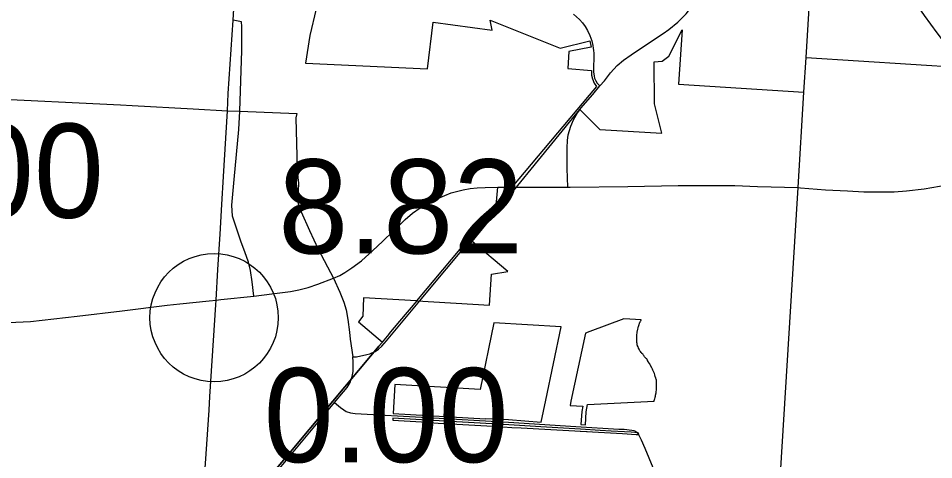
# Model space of a CAD drawing. Extents: x 1729596 to 1934326, y 644115 to 911751.
# Drawn here: x 1834509 to 1845211, y 778685 to 783844 of the extents above; entities that cross this region are included whole.
import ezdxf

# ---------------------------------------------------------------- set-up
doc = ezdxf.new("R2010")
doc.units = 0
for name, color, linetype in [('Default', 7, 'Continuous'), ('GM_X_City_Street', 7, 'Continuous'), ('GM_X_Corporation', 7, 'Continuous'), ('GM_X_County_Road', 7, 'Continuous'), ('GM_X_Interstate_Route', 7, 'Continuous'), ('GM_X_State_Route', 7, 'Continuous'), ('GM_X_Township', 7, 'Continuous')]:
    doc.layers.add(name, color=color, linetype=linetype)

msp = doc.modelspace()

# ---------------------------------------------------------------- linework, layer by layer
at = {"layer": 'Default'}
msp.add_circle((1836798, 780345), 750, dxfattribs=at)
at = {"layer": 'GM_X_City_Street'}
for points in [[(1830888, 782204), (1832249, 782689), (1832627, 782818), (1832829, 782872), (1833025, 782905), (1833227, 782932), (1833389, 782939), (1833673, 782939), (1834091, 782912), (1835705, 782831)], [(1835705, 782831), (1835839, 782824), (1836553, 782786), (1836955, 782764), (1837100, 782758), (1837765, 782732)], [(1840933, 781871), (1840926, 782090), (1840925, 782331), (1840928, 782415), (1840938, 782483), (1840967, 782584), (1840998, 782659), (1841047, 782741), (1841072, 782775)], [(1837765, 782732), (1837753, 782682), (1837765, 782232), (1837770, 782095)], [(1837770, 782095), (1837775, 781981), (1837783, 781922), (1837779, 781819), (1837777, 781733), (1837782, 781676), (1837802, 781618), (1837814, 781583), (1837912, 781362), (1838015, 781147), (1838193, 780805)], [(1840960, 781871), (1841634, 781878), (1842225, 781888), (1842619, 781888), (1842884, 781888), (1843152, 781878), (1843626, 781866), (1843653, 781863)], [(1843653, 781863), (1843947, 781841), (1844201, 781827), (1844395, 781817), (1844535, 781814), (1844750, 781817), (1844893, 781827), (1845099, 781849), (1845367, 781896), (1845750, 781984)], [(1837262, 780598), (1837472, 780623), (1837692, 780652), (1837788, 780671), (1837899, 780697), (1838012, 780736), (1838193, 780805), (1838267, 780838), (1838327, 780874), (1838407, 780927), (1838522, 781011), (1838653, 781132), (1838768, 781235), (1838897, 781361), (1839033, 781492), (1839117, 781565), (1839207, 781627), (1839292, 781682), (1839379, 781723), (1839494, 781774), (1839571, 781804), (1839711, 781841), (1839792, 781854), (1839873, 781862), (1839966, 781866), (1840114, 781870)], [(1840090, 781659), (1840100, 781698), (1840105, 781743), (1840114, 781870)], [(1840114, 781870), (1840114, 781870), (1840273, 781870)], [(1840378, 781870), (1840933, 781871), (1840960, 781871)], [(1843361, 777564), (1843430, 778709), (1843626, 781866)], [(1838193, 780805), (1838268, 780643), (1838314, 780527), (1838341, 780436), (1838361, 780322), (1838379, 780175), (1838390, 780094), (1838419, 779886)], [(1838675, 779950), (1838679, 779951), (1838721, 779977), (1838758, 780012), (1838814, 780076), (1839202, 780542)], [(1838398, 779616), (1838413, 779659), (1838423, 779716), (1838425, 779769), (1838424, 779828), (1838419, 779886)], [(1838419, 779886), (1838461, 779889), (1838582, 779913), (1838619, 779924), (1838675, 779950)], [(1837662, 778703), (1837938, 779032), (1838207, 779353), (1838312, 779478), (1838354, 779530), (1838378, 779568), (1838391, 779594), (1838398, 779616)], [(1838207, 779353), (1838276, 779296), (1838316, 779268), (1838343, 779249), (1838391, 779233), (1838445, 779226), (1839292, 779180), (1840238, 779123), (1841028, 779074), (1841530, 779043), (1841590, 779040), (1841681, 779032), (1841706, 779026), (1841723, 779017), (1841743, 779001)], [(1841743, 779001), (1841743, 779001), (1841760, 778978), (1841792, 778916), (1841834, 778818), (1841974, 778482)], [(1837011, 777935), (1837067, 777991), (1837241, 778192), (1837519, 778532), (1837662, 778703)]]:
    msp.add_lwpolyline(points, dxfattribs=at)
at = {"layer": 'GM_X_Corporation'}
for points in [[(1837990, 783954), (1837918, 783644), (1837865, 783321), (1839293, 783253), (1839358, 783800), (1840047, 783704), (1840026, 783821), (1840842, 783494), (1841189, 783579), (1841206, 783505), (1840944, 783454), (1840934, 783259), (1841208, 783235), (1841210, 783181), (1841220, 783138), (1841242, 783087), (1841269, 783047), (1841184, 782945), (1840280, 781871), (1839165, 780541), (1838544, 780578), (1838538, 780363), (1838485, 780296), (1838765, 780060), (1838745, 780037), (1838742, 780031), (1838725, 780013), (1838668, 779945), (1838625, 779894), (1838186, 779371), (1837650, 778732), (1837174, 778163)], [(1837174, 778163), (1837650, 778732), (1838186, 779371), (1838625, 779894), (1838668, 779945), (1838725, 780013), (1838742, 780031), (1838745, 780037), (1838765, 780060), (1838767, 780058), (1838846, 780153), (1838843, 780156), (1838968, 780306), (1838971, 780303), (1839170, 780540), (1840019, 780491), (1840040, 780852), (1840233, 780886), (1839815, 781235), (1841073, 782777), (1841309, 782546), (1842031, 782501), (1841945, 782843), (1841941, 783336), (1842037, 783342), (1842114, 783400), (1842268, 783711), (1842228, 783073), (1843694, 782979), (1843719, 783387), (1845556, 783268)]]:
    msp.add_lwpolyline(points, dxfattribs=at)
for points in [[(1838890, 779225), (1839969, 779163), (1839969, 779168), (1840239, 779153), (1840620, 779123), (1840675, 779380), (1840855, 780239), (1840069, 780286), (1839907, 779506), (1838909, 779563)], [(1840970, 779369), (1840959, 779320), (1841110, 779309), (1841096, 779248), (1841087, 779095), (1841138, 779092), (1841146, 779243), (1841165, 779331), (1841942, 779371), (1841944, 779376), (1841948, 779388), (1841951, 779398), (1841955, 779413), (1841955, 779414), (1841958, 779426), (1841959, 779436), (1841960, 779440), (1841966, 779468), (1841967, 779474), (1841967, 779484), (1841968, 779496), (1841968, 779507), (1841969, 779514), (1841970, 779522), (1841971, 779532), (1841971, 779535), (1841971, 779551), (1841970, 779593), (1841970, 779603), (1841968, 779613), (1841966, 779626), (1841964, 779635), (1841962, 779639), (1841955, 779659), (1841950, 779678), (1841946, 779691), (1841939, 779707), (1841934, 779717), (1841932, 779723), (1841928, 779732), (1841922, 779745), (1841916, 779757), (1841900, 779787), (1841897, 779793), (1841890, 779804), (1841884, 779814), (1841866, 779846), (1841864, 779849), (1841859, 779856), (1841855, 779862), (1841851, 779865), (1841847, 779870), (1841844, 779872), (1841835, 779883), (1841831, 779888), (1841820, 779903), (1841814, 779910), (1841809, 779917), (1841798, 779927), (1841797, 779929), (1841790, 779938), (1841782, 779950), (1841776, 779959), (1841773, 779964), (1841771, 779969), (1841769, 779972), (1841768, 779975), (1841761, 779987), (1841759, 779993), (1841756, 780002), (1841754, 780006), (1841749, 780017), (1841747, 780021), (1841745, 780025), (1841745, 780027), (1841742, 780036), (1841742, 780044), (1841740, 780055), (1841740, 780061), (1841740, 780063), (1841740, 780070), (1841738, 780090), (1841738, 780093), (1841738, 780099), (1841739, 780112), (1841740, 780136), (1841740, 780140), (1841741, 780150), (1841743, 780164), (1841744, 780176), (1841748, 780194), (1841749, 780200), (1841752, 780208), (1841752, 780210), (1841756, 780227), (1841761, 780247), (1841762, 780250), (1841764, 780257), (1841766, 780263), (1841768, 780271), (1841770, 780276), (1841772, 780283), (1841774, 780288), (1841777, 780293), (1841779, 780298), (1841783, 780304), (1841785, 780307), (1841788, 780313), (1841789, 780316), (1841792, 780320), (1841659, 780327), (1841589, 780331), (1841190, 780184), (1841140, 780165)], [(1838888, 779170), (1838887, 779146), (1839222, 779126), (1839417, 779112), (1839487, 779108), (1839562, 779104), (1839637, 779100), (1839707, 779096), (1839777, 779092), (1839847, 779088), (1839917, 779084), (1839987, 779080), (1840057, 779076), (1840172, 779069), (1840174, 779069), (1840277, 779063), (1840280, 779063), (1840386, 779057), (1840456, 779053), (1840526, 779049), (1840595, 779045), (1840665, 779041), (1840735, 779037), (1840805, 779033), (1840874, 779029), (1840944, 779025), (1841014, 779021), (1841079, 779018), (1841081, 779017), (1841083, 779017), (1841153, 779013), (1841156, 779013), (1841158, 779013), (1841223, 779009), (1841292, 779006), (1841362, 779002), (1841432, 778998), (1841501, 778994), (1841571, 778990), (1841732, 778980), (1841765, 778979), (1841755, 779000), (1841675, 779005), (1841439, 779020), (1841311, 779027), (1841080, 779042), (1840617, 779071), (1840183, 779097), (1839224, 779152)]]:
    msp.add_lwpolyline(points, close=True, dxfattribs=at)
at = {"layer": 'GM_X_County_Road'}
for points in [[(1845531, 783302), (1845441, 783422), (1845252, 783676), (1845103, 783878), (1845012, 784005), (1844911, 784131), (1844769, 784320), (1844631, 784501), (1844451, 784757), (1844268, 785009), (1844121, 785212), (1843999, 785361), (1843954, 785418), (1843915, 785461)], [(1841308, 783054), (1841360, 783114), (1841434, 783206), (1841511, 783291), (1841584, 783354), (1841672, 783417), (1841829, 783524), (1842048, 783668), (1842113, 783713), (1842218, 783797), (1842316, 783897), (1842383, 783983), (1842415, 784029), (1842495, 784159), (1842518, 784205)], [(1841001, 783894), (1841068, 783830), (1841103, 783792), (1841135, 783749), (1841164, 783700), (1841192, 783642), (1841213, 783581), (1841227, 783525), (1841231, 783496), (1841234, 783467), (1841236, 783438), (1841235, 783218), (1841240, 783168), (1841245, 783146), (1841249, 783135), (1841259, 783112), (1841275, 783087), (1841308, 783054)], [(1841072, 782775), (1841086, 782794), (1841225, 782955), (1841308, 783054)], [(1840273, 781870), (1840318, 781870), (1840378, 781870)], [(1840053, 781560), (1840062, 781581), (1840072, 781607), (1840088, 781652), (1840090, 781659)], [(1839781, 781234), (1839795, 781251), (1839953, 781436), (1840049, 781552), (1840053, 781560)], [(1839202, 780542), (1839276, 780630), (1839733, 781176), (1839781, 781234)]]:
    msp.add_lwpolyline(points, dxfattribs=at)
at = {"layer": 'GM_X_Interstate_Route'}
for points in [[(1837020, 783821), (1837027, 783953), (1837045, 784237), (1837075, 784514), (1837141, 784917), (1837223, 785347)], [(1836817, 780494), (1836820, 780550), (1836840, 780909), (1836868, 781322), (1836890, 781668), (1836906, 781995), (1836955, 782764), (1836962, 782965), (1837020, 783821)], [(1836705, 778752), (1836739, 779265), (1836749, 779422), (1836817, 780494)], [(1836655, 778007), (1836686, 778478), (1836705, 778752)]]:
    msp.add_lwpolyline(points, dxfattribs=at)
at = {"layer": 'GM_X_State_Route'}
for points in [[(1837100, 782758), (1837122, 783468), (1837121, 783747), (1837119, 783802), (1837020, 783821)], [(1837005, 781660), (1837033, 781960), (1837087, 782544), (1837100, 782758)], [(1837262, 780598), (1837243, 780763), (1837224, 780898), (1837199, 780995), (1837156, 781115), (1837115, 781226), (1837051, 781415), (1837014, 781532), (1837005, 781660)], [(1834309, 780283), (1834652, 780302), (1835197, 780361), (1835722, 780425), (1836249, 780492), (1836397, 780507)], [(1836397, 780507), (1836740, 780542), (1836820, 780550), (1836877, 780557), (1837262, 780598)]]:
    msp.add_lwpolyline(points, dxfattribs=at)
at = {"layer": 'GM_X_Township'}
msp.add_lwpolyline([(1843361, 777564), (1843430, 778709), (1843626, 781866), (1843694, 782979), (1843719, 783387), (1843850, 785510), (1843918, 786568), (1844278, 791160), (1844305, 791617), (1844418, 793241), (1844463, 793924), (1844479, 794298), (1844500, 794432), (1844507, 794629), (1844527, 794924), (1844609, 797255), (1844685, 798421), (1844785, 799970), (1845145, 805182)], dxfattribs=at)

# ---------------------------------------------------------------- texts
at = {"layer": 'Default'}
for s, p in [('8.00', (1832646, 781513)), ('8.82', (1837548, 781095)), ('0.00', (1837377, 778656))]:
    msp.add_text(s, height=1100, dxfattribs=at).set_placement(p)

doc.saveas('drawing.dxf')
